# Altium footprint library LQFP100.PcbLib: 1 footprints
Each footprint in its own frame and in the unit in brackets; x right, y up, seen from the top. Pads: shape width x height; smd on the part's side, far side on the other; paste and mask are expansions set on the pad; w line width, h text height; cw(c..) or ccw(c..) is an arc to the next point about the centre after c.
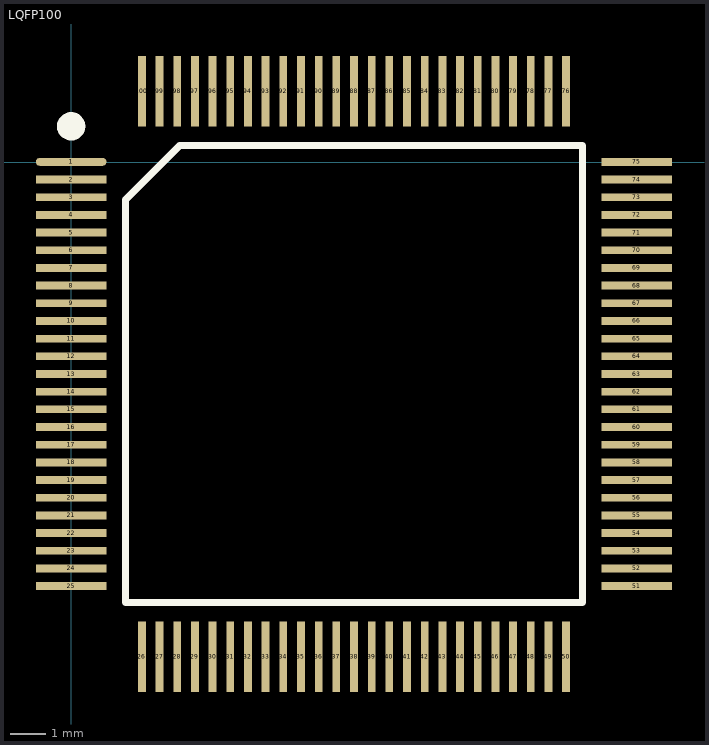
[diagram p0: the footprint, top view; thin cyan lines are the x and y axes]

## LQFP100 [mm]
pads (100):
  oval 2x0.22 smd: 1(0,0.01)
  rect 2x0.22 smd: 2(0,-0.49) 3(0,-0.99) 4(0,-1.49) 5(0,-1.99) 6(0,-2.49) 7(0,-2.99) 8(0,-3.49) 9(0,-3.99) 10(0,-4.49) 11(0,-4.99) 12(0,-5.49) 13(0,-5.99) 14(0,-6.49) 15(0,-6.99) 16(0,-7.49) 17(0,-7.99) 18(0,-8.49) 19(0,-8.99) 20(0,-9.49) 21(0,-9.99) 22(0,-10.49) 23(0,-10.99) 24(0,-11.49) 25(0,-11.99) 51(16,-11.99) 52(16,-11.49) 53(16,-10.99) 54(16,-10.49) 55(16,-9.99) 56(16,-9.49) 57(16,-8.99) 58(16,-8.49) 59(16,-7.99) 60(16,-7.49) 61(16,-6.99) 62(16,-6.49) 63(16,-5.99) 64(16,-5.49) 65(16,-4.99) 66(16,-4.49) 67(16,-3.99) 68(16,-3.49) 69(16,-2.99) 70(16,-2.49) 71(16,-1.99) 72(16,-1.49) 73(16,-0.99) 74(16,-0.49) 75(16,0.01)
  rect 0.22x2 smd: 26(2,-13.99) 27(2.5,-13.99) 28(3,-13.99) 29(3.5,-13.99) 30(4,-13.99) 31(4.5,-13.99) 32(5,-13.99) 33(5.5,-13.99) 34(6,-13.99) 35(6.5,-13.99) 36(7,-13.99) 37(7.5,-13.99) 38(8,-13.99) 39(8.5,-13.99) 40(9,-13.99) 41(9.5,-13.99) 42(10,-13.99) 43(10.5,-13.99) 44(11,-13.99) 45(11.5,-13.99) 46(12,-13.99) 47(12.5,-13.99) 48(13,-13.99) 49(13.5,-13.99) 50(14,-13.99) 76(14,2.01) 77(13.5,2.01) 78(13,2.01) 79(12.5,2.01) 80(12,2.01) 81(11.5,2.01) 82(11,2.01) 83(10.5,2.01) 84(10,2.01) 85(9.5,2.01) 86(9,2.01) 87(8.5,2.01) 88(8,2.01) 89(7.5,2.01) 90(7,2.01) 91(6.5,2.01) 92(6,2.01) 93(5.5,2.01) 94(5,2.01) 95(4.5,2.01) 96(4,2.01) 97(3.5,2.01) 98(3,2.01) 99(2.5,2.01) 100(2,2.01)
Top Overlay:
  circle w0.4: c0,1.016 r0.2
  lines w0.2: 1.535,-12.455 14.465,-12.455 14.465,0.475 3.07,0.475 1.535,-1.06 1.535,-12.455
